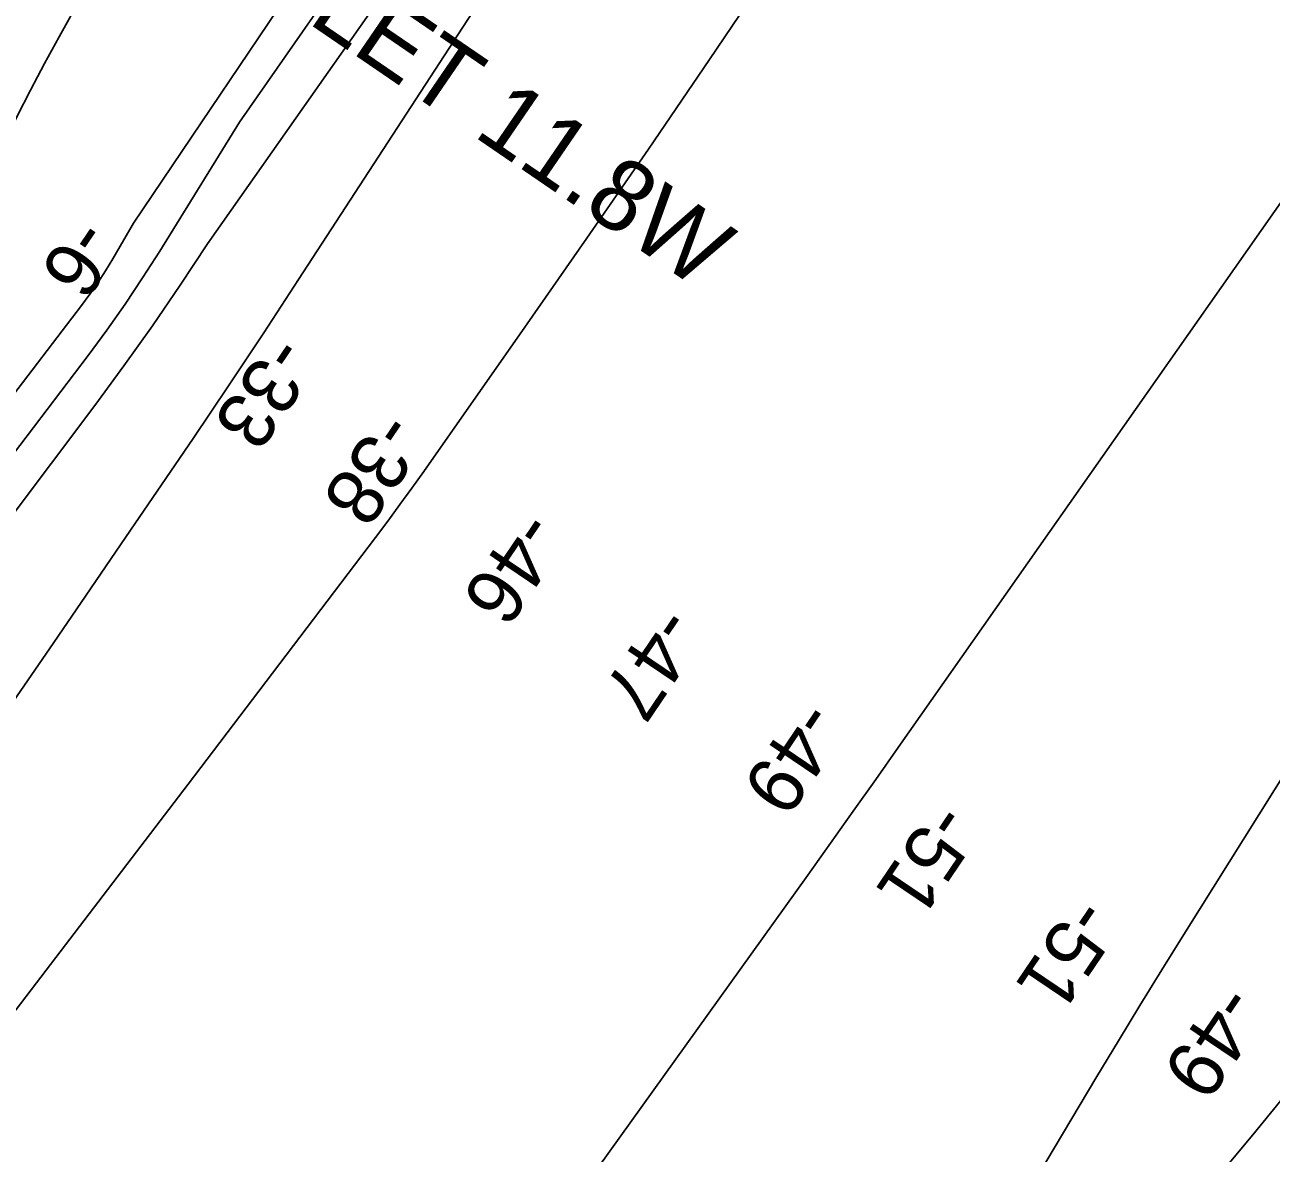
# Model space of a CAD drawing. Extents: x 3905714 to 3926767, y 183354 to 205755.
# Drawn here: x 3913459 to 3914196, y 188893 to 189560 of the extents above; entities that cross this region are included whole.
import ezdxf

# ---------------------------------------------------------------- set-up
doc = ezdxf.new("R2010")
doc.units = 0
for name, color, linetype in [('V-RIVR-JETY', 7, 'Continuous'), ('V-RIVR-RANG', 7, 'Continuous'), ('V-TOPO-DPTH', 7, 'Continuous'), ('V-TOPO-MAJR', 7, 'Continuous'), ('V-TOPO-MINR', 7, 'Continuous')]:
    doc.layers.add(name, color=color, linetype=linetype)

msp = doc.modelspace()

# ---------------------------------------------------------------- linework, layer by layer
at = {"layer": 'V-TOPO-DPTH'}
for points in [[(3913151.89, 188719.91), (3913452.61, 189159.78), (3913473.85, 189190.84), (3913495.09, 189221.9), (3913516.34, 189252.96), (3913537.6, 189284.02), (3913558.74, 189315.14), (3913579.75, 189346.37), (3913600.53, 189377.74), (3913621.16, 189409.2), (3913990.61, 189976.85), (3913991.96, 189978.96), (3913993.3, 189981.08), (3913994.61, 189983.22), (3913995.9, 189985.36), (3913997.19, 189987.51), (3913998.52, 189989.63), (3913999.88, 189991.73), (3914001.27, 189993.82), (3914007.13, 190002.45), (3914007.45, 190002.72), (3914007.65, 190002.78), (3914008.82, 190002.72), (3914466.37, 190645.48)], [(3913151.89, 188719.91), (3913452.61, 189159.78), (3913473.85, 189190.84), (3913495.09, 189221.9), (3913516.34, 189252.96), (3913537.6, 189284.02), (3913558.74, 189315.14), (3913579.75, 189346.37), (3913600.53, 189377.74), (3913621.16, 189409.2), (3913990.61, 189976.85), (3913991.96, 189978.96), (3913993.3, 189981.08), (3913994.61, 189983.22), (3913995.9, 189985.36), (3913997.19, 189987.51), (3913998.52, 189989.63), (3913999.88, 189991.73), (3914001.27, 189993.82), (3914007.13, 190002.45), (3914007.45, 190002.72), (3914007.65, 190002.78), (3914008.82, 190002.72), (3914466.37, 190645.48)], [(3913118.56, 188826.23), (3913500.65, 189334.62), (3913517.9, 189358.09), (3913534.8, 189381.8), (3913551.18, 189405.87), (3913567.22, 189430.18), (3914002.78, 190050.13), (3914130.11, 190226.56), (3914152.91, 190258.95), (3914175.19, 190291.69)], [(3914175.19, 190291.69), (3914152.91, 190258.95), (3914130.11, 190226.56), (3914002.78, 190050.13), (3913567.22, 189430.18), (3913551.18, 189405.87), (3913534.8, 189381.8), (3913517.9, 189358.09), (3913500.65, 189334.62), (3913118.56, 188826.23)], [(3914375.67, 190294.99), (3914157.79, 189976.78), (3914140.37, 189951.25), (3914123, 189925.68), (3914105.71, 189900.04), (3914088.48, 189874.38), (3913899.97, 189592.54), (3913864.13, 189539.35), (3913828.05, 189486.32), (3913791.61, 189433.53), (3913754.93, 189380.91), (3913695.09, 189295.67), (3913688.1, 189285.83), (3913681.04, 189276.04), (3913673.87, 189266.33), (3913666.62, 189256.67), (3913597.65, 189165.74), (3913555.82, 189110.7), (3913513.93, 189055.69), (3913471.94, 189000.76), (3913429.9, 188945.87), (3913226.49, 188680.76)], [(3913226.49, 188680.76), (3913429.9, 188945.87), (3913471.94, 189000.76), (3913513.93, 189055.69), (3913555.82, 189110.7), (3913597.65, 189165.74), (3913666.62, 189256.67), (3913673.87, 189266.33), (3913681.04, 189276.04), (3913688.1, 189285.83), (3913695.09, 189295.67), (3913754.93, 189380.91), (3913791.61, 189433.53), (3913828.05, 189486.32), (3913864.13, 189539.35), (3913899.97, 189592.54), (3914088.48, 189874.38), (3914105.71, 189900.04), (3914123, 189925.68), (3914140.37, 189951.25), (3914157.79, 189976.78), (3914375.67, 190294.99)], [(3913956.3, 190084.49), (3913523.53, 189442.45), (3913511.33, 189421.39), (3913507.03, 189414.27), (3913502.54, 189407.28), (3913497.79, 189400.46), (3913492.87, 189393.76), (3913446.43, 189333.14), (3913418.23, 189296.15), (3913390.16, 189259.07), (3913362.26, 189221.86), (3913334.48, 189184.56), (3913055.99, 188808.7)]]:
    msp.add_lwpolyline(points, dxfattribs=at)
at = {"layer": 'V-TOPO-MAJR'}
for points in [[(3914205.98, 189460.68), (3914166.64, 189404.52), (3913975.71, 189132.53), (3913962.38, 189113.6), (3913949.01, 189094.7), (3913935.59, 189075.83), (3913922.13, 189057), (3913485.45, 188447.98)], [(3914201.86, 188923.68), (3914185.31, 188903.29), (3914168.44, 188883.16), (3913984.03, 188668.11), (3913976.4, 188664.31), (3913969.59, 188663.63), (3913964.02, 188667.6), (3913959.27, 188674.69), (3913958.16, 188688.87), (3913959.05, 188702.71), (3913962.93, 188716.02), (3913968.8, 188728.98), (3914093.14, 188937.79), (3914105.81, 188958.9), (3914118.58, 188979.96), (3914131.5, 189000.93), (3914144.51, 189021.83), (3914215.72, 189135.36)]]:
    msp.add_lwpolyline(points, dxfattribs=at)
at = {"layer": 'V-TOPO-MINR'}
for points in [[(3914466.37, 190645.48), (3914008.82, 190002.72), (3914007.65, 190002.78), (3914007.45, 190002.72), (3914007.13, 190002.45), (3914001.27, 189993.82), (3913999.88, 189991.73), (3913998.52, 189989.63), (3913997.19, 189987.51), (3913995.9, 189985.36), (3913994.61, 189983.22), (3913993.3, 189981.08), (3913991.96, 189978.96), (3913990.61, 189976.85), (3913621.16, 189409.2), (3913600.53, 189377.74), (3913579.75, 189346.37), (3913558.74, 189315.14), (3913537.6, 189284.02), (3913516.34, 189252.96), (3913495.09, 189221.9), (3913473.85, 189190.84), (3913452.61, 189159.78), (3913151.89, 188719.91)], [(3914134.9, 190292.29), (3914121.52, 190271.31), (3914108.22, 190250.28), (3914094.79, 190229.33), (3914081.09, 190208.56), (3914066.99, 190188.07), (3914052.62, 190167.75), (3913980.61, 190067.97), (3913586.17, 189502.32), (3913539.01, 189425.96), (3913528.94, 189410.17), (3913518.58, 189394.6), (3913507.78, 189379.32), (3913496.67, 189364.25), (3913359.26, 189183.27), (3913306.53, 189113.47), (3913254.02, 189043.51), (3913201.85, 188973.29), (3913149.89, 188902.92), (3913060.6, 188781.35)], [(3914175.19, 190291.69), (3914152.91, 190258.95), (3914130.11, 190226.56), (3914002.78, 190050.13), (3913567.22, 189430.18), (3913551.18, 189405.87), (3913534.8, 189381.8), (3913517.9, 189358.09), (3913500.65, 189334.62), (3913118.56, 188826.23)], [(3914375.67, 190294.99), (3914157.79, 189976.78), (3914140.37, 189951.25), (3914123, 189925.68), (3914105.71, 189900.04), (3914088.48, 189874.38), (3913899.97, 189592.54), (3913864.13, 189539.35), (3913828.05, 189486.32), (3913791.61, 189433.53), (3913754.93, 189380.91), (3913695.09, 189295.67), (3913688.1, 189285.83), (3913681.04, 189276.04), (3913673.87, 189266.33), (3913666.62, 189256.67), (3913597.65, 189165.74), (3913555.82, 189110.7), (3913513.93, 189055.69), (3913471.94, 189000.76), (3913429.9, 188945.87), (3913226.49, 188680.76)], [(3913956.3, 190084.49), (3913523.53, 189442.45), (3913511.33, 189421.39), (3913507.03, 189414.27), (3913502.54, 189407.28), (3913497.79, 189400.46), (3913492.87, 189393.76), (3913446.43, 189333.14), (3913418.23, 189296.15), (3913390.16, 189259.07), (3913362.26, 189221.86), (3913334.48, 189184.56), (3913055.99, 188808.7)], [(3913560.3, 189698.56), (3913479.49, 189552.68), (3913470.96, 189536.99), (3913462.61, 189521.21), (3913454.51, 189505.29), (3913446.58, 189489.29), (3913443.58, 189483.11), (3913436.83, 189470.43), (3913429.49, 189458.12), (3913421.25, 189446.4), (3913412.42, 189435.06), (3913316.52, 189320.98), (3913303.87, 189307.49), (3913290.37, 189295.03), (3913275.61, 189284.1), (3913260, 189274.19), (3913227.47, 189255.95)]]:
    msp.add_lwpolyline(points, dxfattribs=at)

# ---------------------------------------------------------------- texts
at = {"layer": 'V-RIVR-JETY'}
msp.add_text('OUTLET 11.8W', height=41.9999, rotation=325.62845, dxfattribs=at).set_placement((3913527.93, 189628.36))
at = {"layer": 'V-RIVR-RANG'}
for s, rotation, p in [('-6', 235.78833, (3913489.93, 189447.11)), ('-33', 235.92869, (3913606.11, 189378.16)), ('-38', 235.92869, (3913670.47, 189333.02)), ('-46', 235.92869, (3913753.19, 189274.5)), ('-47', 235.92869, (3913834.92, 189217.93)), ('-49', 235.92869, (3913918.75, 189162.3)), ('-51', 235.92869, (3913997.82, 189101.79)), ('-51', 235.92869, (3914080.64, 189045.74)), ('-49', 235.92869, (3914167.13, 188994.23))]:
    msp.add_text(s, height=33.5, rotation=rotation, dxfattribs=at).set_placement(p)

doc.saveas('drawing.dxf')
